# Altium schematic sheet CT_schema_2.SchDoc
size 273 x 214 mm
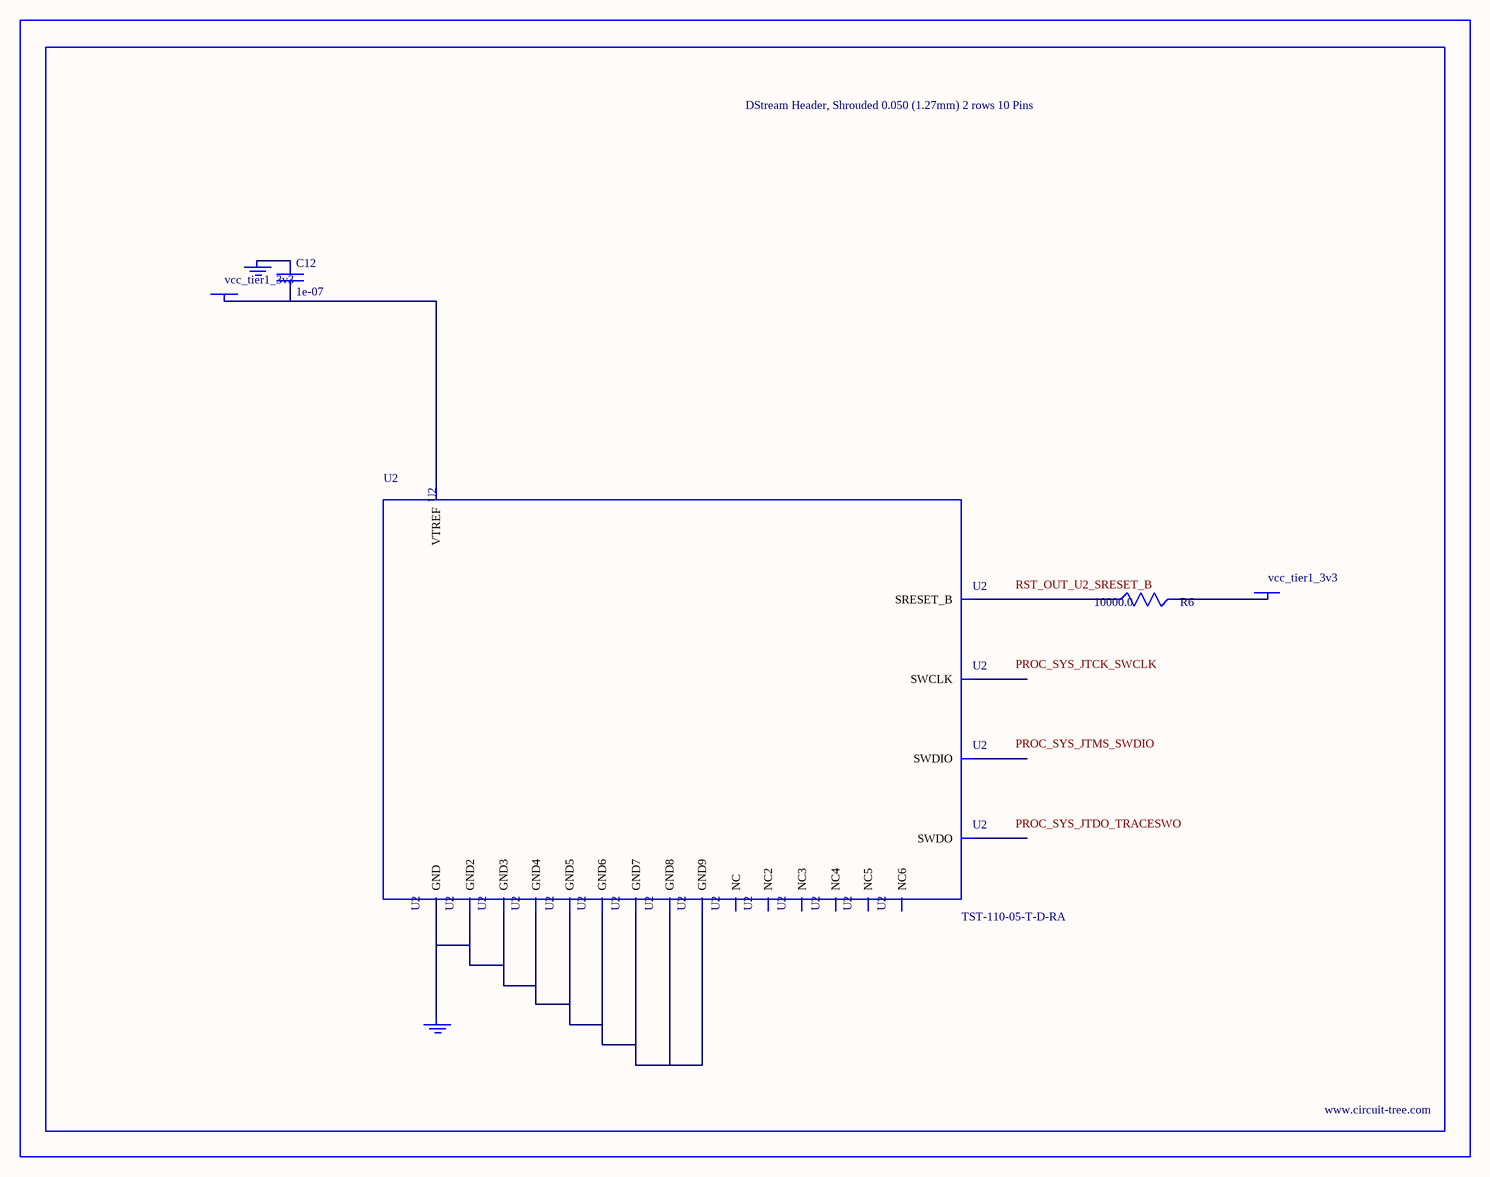
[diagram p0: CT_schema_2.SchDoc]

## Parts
BORDER1  (no value)
C12  1e-07  [C0402]
GND_INSTANCE_1_0  (no value)
GND_INSTANCE_1_1  (no value)
POWER_INSTANCE_1_0  vcc_tier1_3v3
POWER_INSTANCE_1_1  vcc_tier1_3v3
R6  10000.0  [R0603]
U2  TST-110-05-T-D-RA  [TST-110-05-T-D-RA]

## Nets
NetC12_1: C12.1 GND_INSTANCE_1_0.0(GND)
NetC12_2: C12.2 POWER_INSTANCE_1_0.0(PWR) U2.1(VTREF)
NetGND_INSTANCE_1_1_0: GND_INSTANCE_1_1.0(GND) U2.4(GND) U2.6(GND2) U2.8(GND3) U2.10(GND4) U2.12(GND5) U2.14(GND6) U2.16(GND7) U2.18(GND8) U2.20(GND9)
NetPOWER_INSTANCE_1_1_0: POWER_INSTANCE_1_1.0(PWR) R6.2
NetR6_1: R6.1 U2.15(SRESET_B)

Not connected (* = marked no-connect by the designer): U2 2(NC) 3(NC2) 5(NC3) 7(SWDIO) 9(SWCLK) 11(NC4) 13(SWDO) 17(NC5) 19(NC6)

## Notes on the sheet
- Labels drawn without touching a wire or pin: PROC_SYS_JTCK_SWCLK, PROC_SYS_JTDO_TRACESWO, PROC_SYS_JTMS_SWDIO, RST_OUT_U2_SRESET_B

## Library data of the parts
BORDER1 = BORDER_PAGE1
C12 = C0402C104K3RACTU
GND_INSTANCE_1_0 GND_INSTANCE_1_1 = GND
POWER_INSTANCE_1_0 POWER_INSTANCE_1_1 = PWR
R6 = RC0603JR-0710KL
